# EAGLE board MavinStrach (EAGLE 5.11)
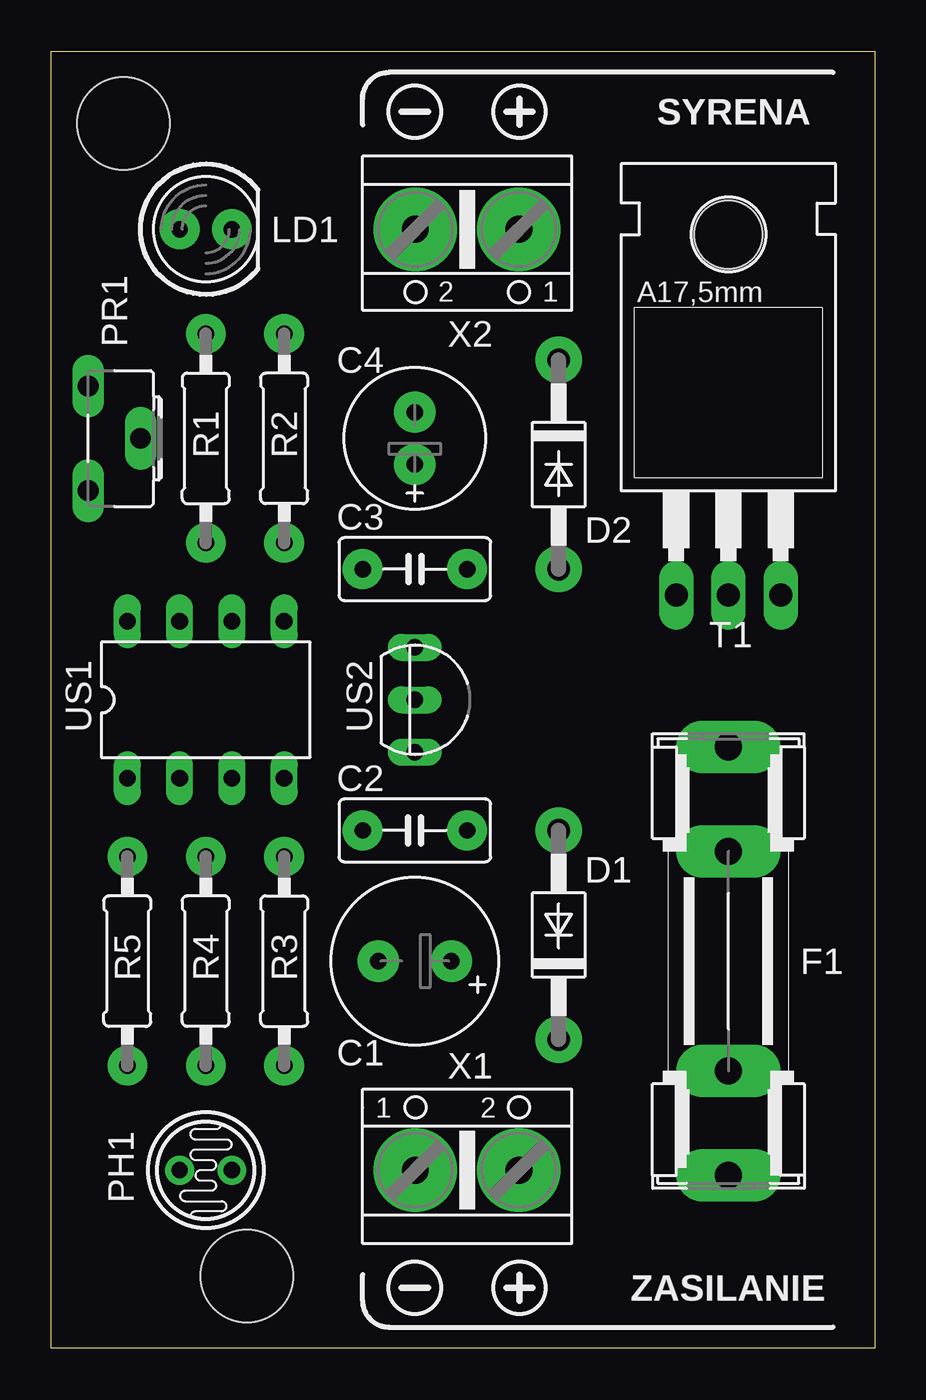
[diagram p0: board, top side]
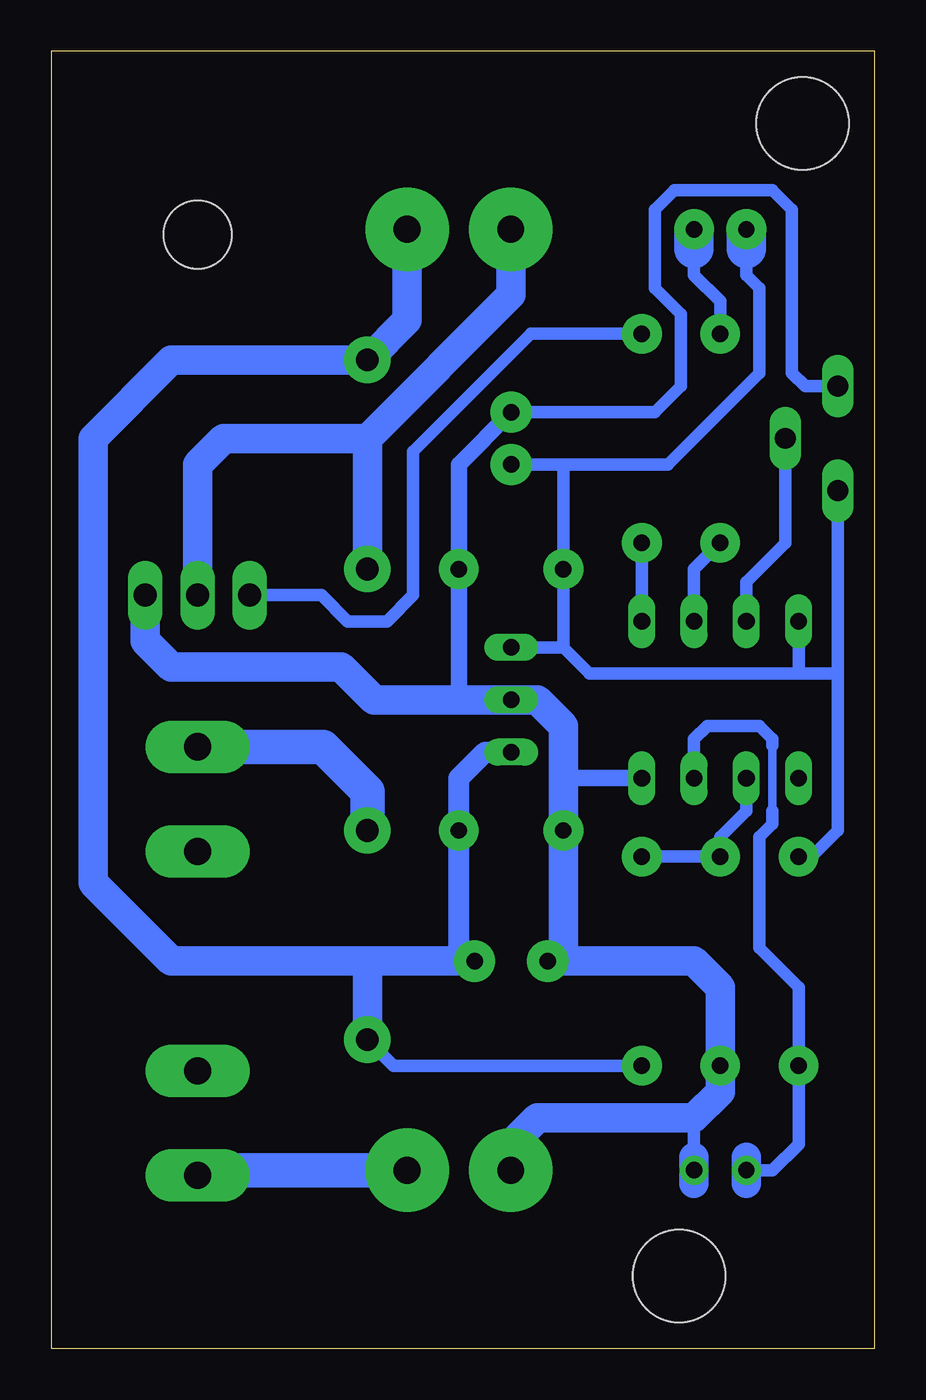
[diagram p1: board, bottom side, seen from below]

Size 40 x 63 mm. Coordinates in mm from the lower left corner, seen from the top.
Outline: 0,63 40,63 40,0 0,0 0,63
Copper layers (1*16): Top 0.035mm / dielectric 1.5mm / Bottom 0.035mm
Design rules "AVT": minimum track width 16mil, minimum drill 19mil, track to track 10mil, track to pad 10mil, pad to pad 10mil, via to via 10mil, smd to smd 10mil, copper to edge 20mil, drill to drill 10mil, minimum pad ring 10mil, minimum via ring 10mil, stop-mask expansion 4mil, vias tented up to drill 0mil, thermal gap 10mil
Holes 4.5 mm at 3.5,59.5 9.5,3.5

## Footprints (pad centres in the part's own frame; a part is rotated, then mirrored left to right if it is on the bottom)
E3,5-8 = drill 0.8 pad 2 round: + -1.778,0; - 1.778,0
C050-030X075 = drill 0.8 pad 1.93 round: 1 -2.54,0; 2 2.54,0
E2,5-7 = drill 0.8 pad 2 round: + -1.27,0; - 1.27,0
DO41-10 = drill 1.1 pad 2.25 round: A 5.08,0; C -5.08,0
SHK20L = drill 1.321 pad 2.54 long: 1A -10.414,0; 1B -5.334,0; 2A 10.414,0; 2B 5.334,0
LED5MM = drill 0.8 pad 1.93 round: A -1.27,0; K 1.27,0
TO46-VT200 = drill 0.8 pad 1.4 round: 1 -1.27,0; 2 1.27,0
CA6H = drill 1.016 long: A -2.54,0; E 2.54,0; S 0,2.54
0207/10 = drill 0.8 pad 1.93 round: 1 -5.08,0; 2 5.08,0
TO220BH = drill 1.118 long: D 0,-6.35; G -2.54,-6.35; S 2.54,-6.35 | hole 3.302: 0,11.176
DIL08 = drill 0.813 long: 1 -3.81,-3.81; 2 -1.27,-3.81; 3 1.27,-3.81; 4 3.81,-3.81; 5 3.81,3.81; 6 1.27,3.81; 7 -1.27,3.81; 8 -3.81,3.81
TO92-78LXX = drill 0.8 long: GND 0,0; IN 2.54,0; OUT -2.54,0
AK500/2 = drill 1.3 pad 4.064 round: 1 -2.515,0; 2 2.515,0

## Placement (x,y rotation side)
C1  470u  [E3,5-8]  17.66,18.8 180 top
C2  100n  [C050-030X075]  17.66,25.15 180 top
C3  100n  [C050-030X075]  17.66,37.85 0 top
C4  100u  [E2,5-7]  17.66,44.2 90 top
D1  1N4007  [DO41-10]  24.64,20.07 90 top
D2  1N4007  [DO41-10]  24.64,42.93 270 top
F1  2A  [SHK20L]  32.9,18.8 90 top
LD1  Y  [LED5MM]  7.5,54.36 0 top
PH1  GL5616D  [TO46-VT200]  7.5,8.64 0 top
PR1  1M  [CA6H]  1.79,44.2 270 top
R1  1k  [0207/10]  7.5,44.2 270 top
R2  1k  [0207/10]  11.31,44.2 90 top
R3  1M  [0207/10]  11.31,18.8 270 top
R4  100k  [0207/10]  7.5,18.8 90 top
R5  100k  [0207/10]  3.69,18.8 90 top
T1  BUZ11  [TO220BH]  32.9,42.93 0 top
US1  ATTINY25  [DIL08]  7.5,31.5 0 top
US2  LM2931  [TO92-78LXX]  17.66,31.5 270 top
X1  Zasilanie  [AK500/2]  20.2,8.64 0 top
X2  Syrena  [AK500/2]  20.2,54.36 180 top

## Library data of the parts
C1-C4 R1-R5 = rcl
D1 D2 = diode
F1 = fuse; OC_FARNELL: unknown; OC_NEWARK: unknown
LD1 = led
PH1 = photo-elements
PR1 = pot
T1 = transistor-power
US1 = atmel; MPN: ATTINY13-20PU; OC_FARNELL: 9171550; OC_NEWARK: 96K6521
US2 = v-reg
X1 X2 = con-ptr500; OC_FARNELL: unknown; OC_NEWARK: unknown

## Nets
+5V: C3.1 C4.+ LD1.A PR1.E R5.2 US1.8 US2.OUT
+12V: C1.+ C2.1 D1.C D2.C R3.2 US2.IN X2.1
FOTO: PH1.1 R5.1 US1.3
GND: C1.- C2.2 C3.2 C4.- PH1.2 PR1.A R4.1 T1.S US1.4 US2.GND X1.1
LED: R1.2 US1.6
N$1: D1.A F1.2A
N$2: F1.1A X1.2
N$3: LD1.K R1.1
N$4: R2.2 T1.G
N$5: D2.A T1.D X2.2
REG: PR1.S US1.7
T: R2.1 US1.5
V: R3.1 R4.2 US1.2

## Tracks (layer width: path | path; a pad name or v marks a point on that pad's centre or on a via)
+5V
  Bottom 0.61: 15.12,42.93 C4.+ | 15.12,42.93 C3.1 15.12,34.04 | 6.23,53.41 6.23,52.14 5.59,51.5 5.59,47.38 10.04,42.93 15.12,42.93 | 15.12,34.04 US2.OUT | 15.12,34.04 13.85,32.77 3.69,32.77 | 3.69,32.77 1.79,32.77 | 1.79,32.77 1.79,25.15 3.05,23.88 R5.2 | 1.79,32.77 PR1.E | US1.8 3.69,32.77
  Bottom 1.93: 6.23,53.41 LD1.A
+12V
  Bottom 0.61: R3.2 23.38,13.72 D1.C
  Bottom 1.016: US2.IN 18.93,28.96 20.2,27.69 C2.1 20.2,18.8
  Bottom 1.422: 24.64,18.8 20.2,18.8 C1.+ | D1.C 24.64,18.8 | 24.64,18.8 34.17,18.8 37.98,22.61 37.98,44.2 34.17,48.01 D2.C 22.71,49.94 X2.1
FOTO
  Bottom 0.406: 4.96,29.28 4.96,26.1
  Bottom 0.61: PH1.1 4.96,8.64 3.69,9.91 R5.1 3.69,17.53 5.59,19.44 5.59,24.83 4.96,25.47 4.96,26.1 | 4.96,29.28 4.96,29.59 5.59,30.23 8.13,30.23 8.77,29.59 US1.3
  Bottom 1.422: 6.23,9.27 PH1.1 6.23,8
GND
  Bottom 0.61: 8.77,11.18 8.77,9.27 | PR1.A 3.37,46.74 4.01,47.38 4.01,55.31 4.96,56.27 9.72,56.27 10.68,55.31 10.68,51.5 9.4,50.23 9.4,46.74 10.68,45.47 C4.-
  Bottom 0.813: C4.- 20.2,42.93 C3.2 20.2,31.5 | US1.4 15.12,27.69
  Bottom 1.27: 17.66,8.64 X1.1
  Bottom 1.422: T1.S 35.44,34.36 34.17,33.09 25.91,33.09 24.33,31.5 20.2,31.5 US2.GND 16.39,31.5 15.12,30.23 15.12,27.69 C2.2 15.12,18.8 | 17.66,8.64 17.66,9.91 16.39,11.18 8.77,11.18 7.5,12.45 R4.1 7.5,17.53 8.77,18.8 15.12,18.8 | 15.12,18.8 C1.- | 8.77,9.27 PH1.2 8.77,8
LED
  Bottom 0.61: US1.6 8.77,37.85 R1.2
N$1
  Bottom 1.676: F1.2A 26.8,29.21 24.64,27.05 D1.A
N$2
  Bottom 1.676: X1.2 32.65,8.64 F1.1A
N$3
  Bottom 0.61: R1.1 7.5,50.87 8.77,52.14 8.77,53.41
  Bottom 1.93: 8.77,53.41 LD1.K
N$4
  Bottom 0.61: T1.G 26.87,36.58 25.6,35.31 23.69,35.31 22.42,36.58 22.42,43.56 16.71,49.28 R2.2
N$5
  Bottom 0.61: 17.66,54.34 X2.2
  Bottom 1.422: D2.A 24.64,44.2 | 24.64,44.2 17.66,51.19 17.66,54.34 | T1.D 32.9,42.93 31.63,44.2 24.64,44.2
REG
  Bottom 0.61: PR1.S 4.33,39.12 6.23,37.22 US1.7
T
  Bottom 0.61: US1.5 R2.1
V
  Bottom 0.61: US1.2 6.23,26.1 7.5,24.83 R4.2 R3.1

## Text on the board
tPlace: SYRENA | ZASILANIE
